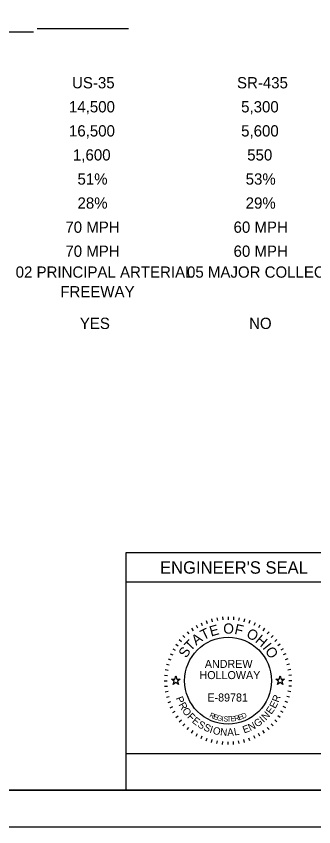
# Model space of a CAD drawing. Extents: x 0 to 34, y 0 to 22.
# Drawn here: x 7.46 to 11.54, y 0 to 11.1 of the extents above; entities that cross this region are included whole.
import ezdxf

# ---------------------------------------------------------------- set-up
doc = ezdxf.new("R2010")
doc.units = 0
for name, color, linetype in [('Default', 7, 'Continuous'), ('SH_Border', 7, 'Continuous'), ('SH_Cut_Line', 7, 'Continuous'), ('SH_Data', 7, 'Continuous'), ('SH_Text', 7, 'Continuous')]:
    doc.layers.add(name, color=color, linetype=linetype)

msp = doc.modelspace()

# ---------------------------------------------------------------- linework, layer by layer
at = {"layer": 'Default'}
for points in [[(9.591, 2.02), (9.638, 2.02), (9.652, 2.065), (9.667, 2.02), (9.713, 2.02), (9.676, 1.992), (9.69, 1.948), (9.652, 1.975), (9.614, 1.948), (9.629, 1.992)], [(11.021, 2.02), (11.068, 2.02), (11.082, 2.065), (11.097, 2.02), (11.143, 2.02), (11.106, 1.992), (11.12, 1.948), (11.082, 1.975), (11.044, 1.948), (11.059, 1.992)]]:
    msp.add_lwpolyline(points, close=True, dxfattribs=at)
at = {"layer": 'SH_Border'}
msp.add_lwpolyline([(1.5, 21.5), (33.5, 21.5), (33.5, 0.5), (1.5, 0.5)], close=True, dxfattribs=at)
at = {"layer": 'SH_Cut_Line'}
msp.add_lwpolyline([(0, 0), (34, 0), (34, 22), (0, 22)], close=True, dxfattribs=at)
at = {"layer": 'SH_Data'}
for p, q in [((7.7, 10.877), (3.347, 10.877)), ((9, 10.922), (7.75, 10.922)), ((11.767, 3.75), (8.967, 3.75)), ((8.967, 3.75), (8.967, 0.5)), ((11.767, 3.35), (8.967, 3.35)), ((9.997, 2.793), (10.014, 2.757)), ((10.068, 2.822), (10.081, 2.785)), ((10.141, 2.845), (10.151, 2.807)), ((10.215, 2.862), (10.222, 2.822)), ((10.291, 2.872), (10.294, 2.832)), ((10.367, 2.875), (10.367, 2.835)), ((10.443, 2.872), (10.44, 2.832)), ((10.519, 2.862), (10.512, 2.822)), ((10.594, 2.845), (10.583, 2.807)), ((10.666, 2.822), (10.653, 2.785)), ((10.737, 2.793), (10.72, 2.757)), ((9.805, 2.67), (9.83, 2.64)), ((9.865, 2.717), (9.888, 2.684)), ((9.93, 2.758), (9.95, 2.723)), ((10.805, 2.758), (10.785, 2.723)), ((10.869, 2.717), (10.846, 2.684)), ((10.929, 2.67), (10.904, 2.64)), ((9.697, 2.562), (9.727, 2.537)), ((9.748, 2.619), (9.777, 2.59)), ((10.986, 2.619), (10.957, 2.59)), ((11.037, 2.562), (11.007, 2.537)), ((9.65, 2.502), (9.683, 2.479)), ((11.084, 2.502), (11.051, 2.479)), ((9.574, 2.37), (9.61, 2.353)), ((9.609, 2.438), (9.644, 2.418)), ((11.125, 2.438), (11.09, 2.418)), ((11.16, 2.37), (11.124, 2.353)), ((9.522, 2.226), (9.56, 2.216)), ((9.545, 2.299), (9.582, 2.286)), ((11.189, 2.299), (11.152, 2.286)), ((11.212, 2.226), (11.174, 2.216)), ((9.505, 2.152), (9.545, 2.145)), ((11.229, 2.152), (11.189, 2.145)), ((9.492, 2), (9.532, 2)), ((9.495, 2.076), (9.535, 2.073)), ((11.239, 2.076), (11.199, 2.073)), ((11.242, 2), (11.202, 2)), ((9.495, 1.924), (9.535, 1.927)), ((11.239, 1.924), (11.199, 1.927)), ((9.505, 1.848), (9.545, 1.855)), ((9.522, 1.774), (9.56, 1.784)), ((11.212, 1.774), (11.174, 1.784)), ((11.229, 1.848), (11.189, 1.855)), ((9.545, 1.701), (9.582, 1.714)), ((11.189, 1.701), (11.152, 1.714)), ((9.574, 1.63), (9.61, 1.647)), ((9.609, 1.563), (9.644, 1.583)), ((11.125, 1.563), (11.09, 1.583)), ((11.16, 1.63), (11.124, 1.647)), ((9.65, 1.498), (9.683, 1.521)), ((9.697, 1.438), (9.727, 1.463)), ((11.037, 1.438), (11.007, 1.463)), ((11.084, 1.498), (11.051, 1.521)), ((9.748, 1.381), (9.777, 1.41)), ((9.805, 1.33), (9.83, 1.36)), ((10.929, 1.33), (10.904, 1.36)), ((10.986, 1.381), (10.957, 1.41)), ((9.865, 1.283), (9.888, 1.316)), ((9.93, 1.242), (9.95, 1.277)), ((9.997, 1.207), (10.014, 1.243)), ((10.737, 1.207), (10.72, 1.243)), ((10.805, 1.242), (10.785, 1.277)), ((10.869, 1.283), (10.846, 1.316)), ((10.068, 1.178), (10.081, 1.215)), ((10.141, 1.155), (10.151, 1.193)), ((10.215, 1.138), (10.222, 1.178)), ((10.291, 1.128), (10.294, 1.168)), ((10.367, 1.125), (10.367, 1.165)), ((10.443, 1.128), (10.44, 1.168)), ((10.519, 1.138), (10.512, 1.178)), ((10.594, 1.155), (10.583, 1.193)), ((10.666, 1.178), (10.653, 1.215)), ((7.127, 0.5), (9.927, 0.5)), ((10.396, 0.5), (7.596, 0.5))]:
    msp.add_line(p, q, dxfattribs=at)
msp.add_lwpolyline([(11.767, 0.5), (11.767, 1), (8.967, 1), (8.967, 0.5)], close=True, dxfattribs=at)
msp.add_circle((10.367, 2), 0.595, dxfattribs=at)

# ---------------------------------------------------------------- texts
for s, height, p in [("ENGINEER'S SEAL", 0.17, (9.435, 3.465)), ('ANDREW', 0.11, (10.049, 2.175)), ('HOLLOWAY', 0.11, (9.976, 2.022)), ('E-89781', 0.11, (10.084, 1.715))]:
    msp.add_text(s, height=height, dxfattribs=at).set_placement(p)
for s, height, rotation, p in [('O', 0.14, 359.7812, (10.302, 2.644)), ('F', 0.14, 347.4362, (10.448, 2.642)), ('T', 0.14, 25.7167, (10.029, 2.552)), ('E', 0.14, 15.7571, (10.135, 2.604)), ('O', 0.14, 332.2586, (10.607, 2.602)), ('T', 0.14, 46.4344, (9.855, 2.396)), ('A', 0.14, 36.4747, (9.93, 2.478)), ('H', 0.14, 319.9136, (10.73, 2.536)), ('S', 0.14, 57.1924, (9.795, 2.301)), ('I', 0.14, 308.367, (10.833, 2.448)), ('O', 0.14, 303.1491, (10.869, 2.409)), ('P', 0.1, 291.494, (9.649, 1.762)), ('R', 0.1, 69.2322, (11.059, 1.695)), ('R', 0.1, 298.7311, (9.686, 1.672)), ('E', 0.1, 61.9951, (11.015, 1.61)), ('O', 0.1, 306.4666, (9.732, 1.588)), ('F', 0.1, 314.7068, (9.801, 1.498)), ('R', 0.07, 334.487, (10.105, 1.505)), ('D', 0.07, 23.3052, (10.568, 1.477)), ('N', 0.1, 47.0224, (10.887, 1.451)), ('E', 0.1, 54.758, (10.96, 1.531)), ('E', 0.1, 321.4393, (9.865, 1.435)), ('S', 0.1, 328.6764, (9.941, 1.375)), ('E', 0.07, 341.04, (10.158, 1.48)), ('G', 0.07, 347.4752, (10.208, 1.462)), ('I', 0.07, 353.7858, (10.276, 1.447)), ('S', 0.07, 356.8926, (10.303, 1.443)), ('T', 0.07, 3.0061, (10.353, 1.439)), ('E', 0.07, 6.0117, (10.406, 1.441)), ('R', 0.07, 11.9184, (10.46, 1.447)), ('E', 0.07, 17.6836, (10.517, 1.46)), ('G', 0.1, 35.0469, (10.765, 1.357)), ('I', 0.1, 43.287, (10.854, 1.421)), ('S', 0.1, 335.9134, (10.023, 1.327)), ('I', 0.1, 343.1505, (10.108, 1.29)), ('O', 0.1, 346.8859, (10.151, 1.275)), ('N', 0.1, 355.1261, (10.256, 1.252)), ('A', 0.1, 2.8617, (10.359, 1.244)), ('L', 0.1, 10.0987, (10.456, 1.249)), ('E', 0.1, 20.0742, (10.588, 1.277)), ('N', 0.1, 27.3113, (10.672, 1.308))]:
    msp.add_text(s, height=height, rotation=rotation, dxfattribs=at).set_placement(p)
at = {"layer": 'SH_Text'}
for s, p in [('US-35', (8.228, 10.109)), ('SR-435', (10.49, 10.109)), ('14,500', (8.186, 9.78)), ('5,300', (10.547, 9.78)), ('16,500', (8.186, 9.45)), ('5,600', (10.547, 9.45)), ('1,600', (8.241, 9.121)), ('550', (10.63, 9.121)), ('51%', (8.303, 8.791)), ('53%', (10.609, 8.791)), ('28%', (8.303, 8.462)), ('29%', (10.609, 8.462)), ('70 MPH', (8.137, 8.132)), ('60 MPH', (10.443, 8.132)), ('70 MPH', (8.137, 7.803)), ('60 MPH', (10.443, 7.803)), ('02 PRINCIPAL ARTERIAL ', (7.455, 7.517)), ('05 MAJOR COLLECTOR', (9.805, 7.517)), ('FREEWAY', (8.067, 7.248)), ('YES', (8.335, 6.815)), ('NO', (10.656, 6.815))]:
    msp.add_text(s, height=0.154, dxfattribs=at).set_placement(p)

doc.saveas('drawing.dxf')
